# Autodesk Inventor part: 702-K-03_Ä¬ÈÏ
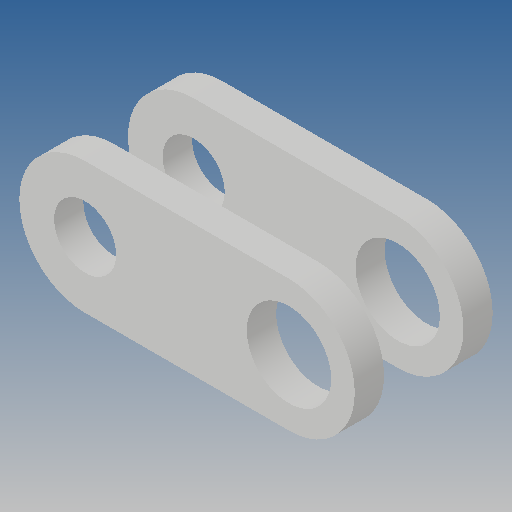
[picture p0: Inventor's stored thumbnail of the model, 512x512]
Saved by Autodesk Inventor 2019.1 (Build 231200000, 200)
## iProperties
Created: 2010-06
Part Number: 702-K-03_Ä¬ÈÏ
Material: Ogólny
Document SubType Name: Modeling
Designer: CADENGINEERING4
Density: 1 g/cm^3
Appearance: Domyślna
Author: CADENGINEERING4
Revision Number: ÈÎºÎ
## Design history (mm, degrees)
feature "NONE"
feature "NONE:1"
node "Bryła1"
node "Bryła2"
